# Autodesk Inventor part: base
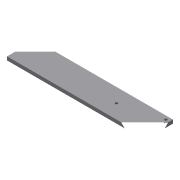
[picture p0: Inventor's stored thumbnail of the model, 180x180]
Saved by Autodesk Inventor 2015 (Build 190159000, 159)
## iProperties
Created: 2016-07
Part Number: base
Material: EIFS, Exterior Insulation
Document SubType Name: Modeling
Designer: user
Density: 0.023 g/cm^3
Appearance: Gray
Author: user
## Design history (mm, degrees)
sketch "Sketch1"
  geometry: L1 (0, 0)-(-247.65, 0); L2 (-247.65, 0)-(-247.65, -50.8); L3 (-247.65, -50.8)-(0, -50.8); L4 (0, -50.8)-(0, 0)
  constraints: 8 end point, 2 parallel, 1 horizontal, 1 perpendicular
  dimensions: "d0" = 247.65 distance of L3.end L2.end; "d1" = 50.8 distance of L2.end L1.end
extrude "Extrusion1" new body sketch "Sketch1" distance "d2" = 6.35; taper "d3" = 0 deg
sketch "Sketch2"
  geometry: C1 r 2.381 at (171.45, 25.4); 1 further point
  constraints: 1 centre point
  dimensions: "d4" = 4.7625 diameter of C1
extrude "Extrusion2" cut sketch "Sketch2" distance "d5" = 6.35; taper "d6" = 0 deg
sketch "Sketch3"
  geometry: C1 r 2.381 at (241.3, 6.35); C2 r 2.381 at (241.3, 44.45); 1 further point
  constraints: 2 centre point
  dimensions: "d7" = 4.7625 diameter of C1; "d8" = 4.7625 diameter of C2
extrude "Extrusion3" cut sketch "Sketch3" distance "d9" = 25.4; taper "d10" = 0 deg
body "Solid1"
